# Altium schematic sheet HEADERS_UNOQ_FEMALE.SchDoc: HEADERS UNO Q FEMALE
size A3; Author: Silvio Navaretti; CompanyName: Arduino SRL; DrawnBy: Silvio Navaretti; Engineer: Silvio Navaretti; Organization: Arduino SRL; DocumentNumber: ASX00083; SheetNumber: 3; SheetTotal: 11; RevAuthor: Silvio Navaretti
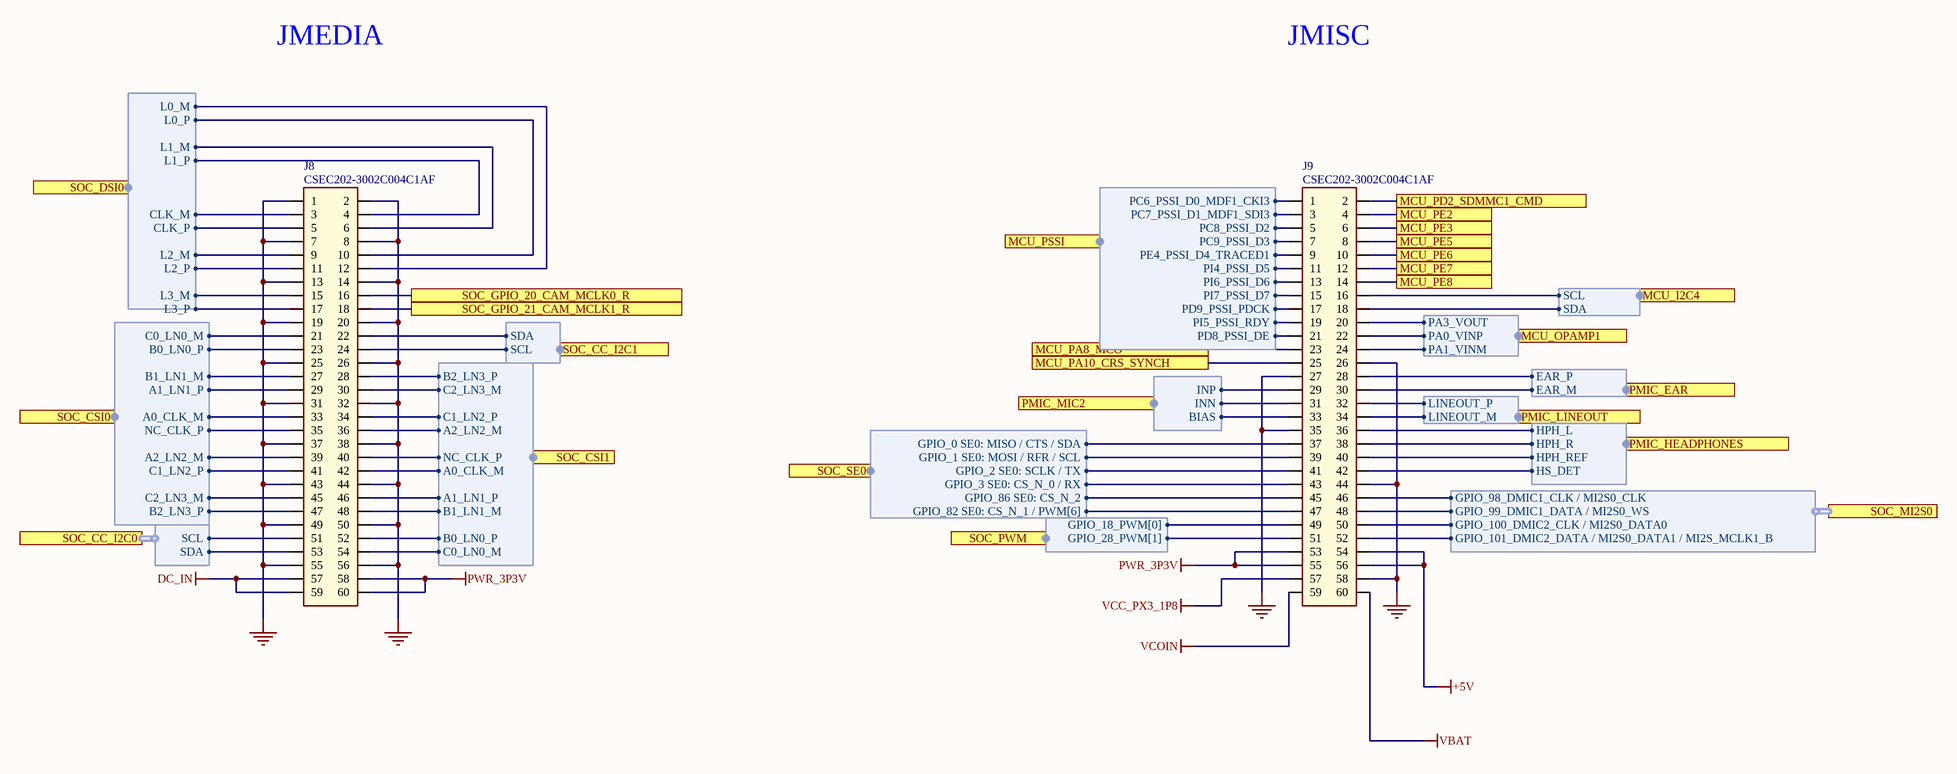
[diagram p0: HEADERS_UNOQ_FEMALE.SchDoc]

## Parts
J8  CSEC202-3002C004C1AF  [CSEC202-3002C004C1AF]
J9  CSEC202-3002C004C1AF  [CSEC202-3002C004C1AF]

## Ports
MCU_I2C4 (harness I2C), MCU_OPAMP1 (harness MCU_OPAMP), MCU_PA8_MCO, MCU_PA10_CRS_SYNCH, MCU_PD2_SDMMC1_CMD, MCU_PE2, MCU_PE3, MCU_PE5, MCU_PE6, MCU_PE7, MCU_PE8, MCU_PSSI (harness PSSI_MCU), PMIC_EAR (harness EAT), PMIC_HEADPHONES (harness HEADPHONES), PMIC_LINEOUT (harness LINEOUT), PMIC_MIC2 (harness MIC), SOC_CC_I2C0 (harness I2C), SOC_CC_I2C1 (harness I2C), SOC_CSI0 (harness IMOLA_CSI), SOC_CSI1 (harness IMOLA_CSI), SOC_DSI0 (harness IMOLA_DSI), SOC_GPIO_20_CAM_MCLK0_R, SOC_GPIO_21_CAM_MCLK1_R, SOC_MI2S0 (harness SOC_I2S), SOC_PWM (harness SOC_PWM), SOC_SE0 (harness SOC_GPIO)

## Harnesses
IMOLA_DSI: L1_P, L1_M, L3_P, L3_M, CLK_P, CLK_M, L0_P, L0_M, L2_P, L2_M
I2C: SDA, SCL
IMOLA_CSI: C2_LN3_M, A2_LN2_M, C1_LN2_P, C0_LN0_M, B0_LN0_P, A0_CLK_M, NC_CLK_P, B1_LN1_M, A1_LN1_P, B2_LN3_P
PSSI_MCU: PC6_PSSI_D0_MDF1_CKI3, PC7_PSSI_D1_MDF1_SDI3, PC8_PSSI_D2, PC9_PSSI_D3, PE4_PSSI_D4_TRACED1, PI4_PSSI_D5, PI6_PSSI_D6, PI7_PSSI_D7, PD9_PSSI_PDCK, PI5_PSSI_RDY, PD8_PSSI_DE
MCU_OPAMP: PA3_VOUT, PA0_VINP, PA1_VINM
EAT: EAR_P, EAR_M
MIC: INP, INN, BIAS
LINEOUT: LINEOUT_P, LINEOUT_M
HEADPHONES: HPH_L, HPH_R, HPH_REF, HS_DET
SOC_GPIO: GPIO_0 SE0: MISO / CTS / SDA, GPIO_1 SE0: MOSI / RFR / SCL, GPIO_2 SE0: SCLK / TX, GPIO_3 SE0: CS_N_0 / RX, GPIO_86 SE0: CS_N_2, GPIO_82 SE0: CS_N_1 / PWM[6]
SOC_PWM: GPIO_18_PWM[0], GPIO_28_PWM[1]
SOC_I2S: GPIO_98_DMIC1_CLK / MI2S0_CLK, GPIO_99_DMIC1_DATA / MI2S0_WS, GPIO_100_DMIC2_CLK / MI2S0_DATA0, GPIO_101_DMIC2_DATA / MI2S0_DATA1 / MI2S_MCLK1_B

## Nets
+5V: J9.54 J9.56
DC_IN: J8.57 J8.59
GND: J8.1 J8.2 J8.7 J8.8 J8.13 J8.14 J8.19 J8.20 J8.25 J8.26 J8.31 J8.32 J8.37 J8.38 J8.43 J8.44 J8.49 J8.50 J8.55 J8.56 J9.26 J9.27 J9.35 J9.44 J9.58
PWR_3P3V: J8.58 J8.60 J9.53 J9.55
VBAT: J9.60
VCC_PX3_1P8: J9.57
VCOIN: J9.59
MCU_PA8_MCO: J9.23 ; port MCU_PA8_MCO
MCU_PA10_CRS_SYNCH: J9.25 ; port MCU_PA10_CRS_SYNCH
MCU_PD2_SDMMC1_CMD: J9.2 ; port MCU_PD2_SDMMC1_CMD
MCU_PE2: J9.4 ; port MCU_PE2
MCU_PE3: J9.6 ; port MCU_PE3
MCU_PE5: J9.8 ; port MCU_PE5
MCU_PE6: J9.10 ; port MCU_PE6
MCU_PE7: J9.12 ; port MCU_PE7
MCU_PE8: J9.14 ; port MCU_PE8
SOC_GPIO_20_CAM_MCLK0_R: J8.16 ; port SOC_GPIO_20_CAM_MCLK0_R
SOC_GPIO_21_CAM_MCLK1_R: J8.18 ; port SOC_GPIO_21_CAM_MCLK1_R
NetJ8_3: J8.3 ; port SOC_DSI0.CLK_M
NetJ8_4: J8.4 ; port SOC_DSI0.L1_P
NetJ8_5: J8.5 ; port SOC_DSI0.CLK_P
NetJ8_6: J8.6 ; port SOC_DSI0.L1_M
NetJ8_9: J8.9 ; port SOC_DSI0.L2_M
NetJ8_10: J8.10 ; port SOC_DSI0.L0_P
NetJ8_11: J8.11 ; port SOC_DSI0.L2_P
NetJ8_12: J8.12 ; port SOC_DSI0.L0_M
NetJ8_15: J8.15 ; port SOC_DSI0.L3_M
NetJ8_17: J8.17 ; port SOC_DSI0.L3_P
NetJ8_21: J8.21 ; port SOC_CSI0.C0_LN0_M
NetJ8_22: J8.22 ; port SOC_CC_I2C1.SDA
NetJ8_23: J8.23 ; port SOC_CSI0.B0_LN0_P
NetJ8_24: J8.24 ; port SOC_CC_I2C1.SCL
NetJ8_27: J8.27 ; port SOC_CSI0.B1_LN1_M
NetJ8_28: J8.28 ; port SOC_CSI1.B2_LN3_P
NetJ8_29: J8.29 ; port SOC_CSI0.A1_LN1_P
NetJ8_30: J8.30 ; port SOC_CSI1.C2_LN3_M
NetJ8_33: J8.33 ; port SOC_CSI0.A0_CLK_M
NetJ8_34: J8.34 ; port SOC_CSI1.C1_LN2_P
NetJ8_35: J8.35 ; port SOC_CSI0.NC_CLK_P
NetJ8_36: J8.36 ; port SOC_CSI1.A2_LN2_M
NetJ8_39: J8.39 ; port SOC_CSI0.A2_LN2_M
NetJ8_40: J8.40 ; port SOC_CSI1.NC_CLK_P
NetJ8_41: J8.41 ; port SOC_CSI0.C1_LN2_P
NetJ8_42: J8.42 ; port SOC_CSI1.A0_CLK_M
NetJ8_45: J8.45 ; port SOC_CSI0.C2_LN3_M
NetJ8_46: J8.46 ; port SOC_CSI1.A1_LN1_P
NetJ8_47: J8.47 ; port SOC_CSI0.B2_LN3_P
NetJ8_48: J8.48 ; port SOC_CSI1.B1_LN1_M
NetJ8_51: J8.51 ; port SOC_CC_I2C0.SCL
NetJ8_52: J8.52 ; port SOC_CSI1.B0_LN0_P
NetJ8_53: J8.53 ; port SOC_CC_I2C0.SDA
NetJ8_54: J8.54 ; port SOC_CSI1.C0_LN0_M
NetJ9_1: J9.1 ; port MCU_PSSI.PC6_PSSI_D0_MDF1_CKI3
NetJ9_3: J9.3 ; port MCU_PSSI.PC7_PSSI_D1_MDF1_SDI3
NetJ9_5: J9.5 ; port MCU_PSSI.PC8_PSSI_D2
NetJ9_7: J9.7 ; port MCU_PSSI.PC9_PSSI_D3
NetJ9_9: J9.9 ; port MCU_PSSI.PE4_PSSI_D4_TRACED1
NetJ9_11: J9.11 ; port MCU_PSSI.PI4_PSSI_D5
NetJ9_13: J9.13 ; port MCU_PSSI.PI6_PSSI_D6
NetJ9_15: J9.15 ; port MCU_PSSI.PI7_PSSI_D7
NetJ9_16: J9.16 ; port MCU_I2C4.SCL
NetJ9_17: J9.17 ; port MCU_PSSI.PD9_PSSI_PDCK
NetJ9_18: J9.18 ; port MCU_I2C4.SDA
NetJ9_19: J9.19 ; port MCU_PSSI.PI5_PSSI_RDY
NetJ9_20: J9.20 ; port MCU_OPAMP1.PA3_VOUT
NetJ9_21: J9.21 ; port MCU_PSSI.PD8_PSSI_DE
NetJ9_22: J9.22 ; port MCU_OPAMP1.PA0_VINP
NetJ9_24: J9.24 ; port MCU_OPAMP1.PA1_VINM
NetJ9_28: J9.28 ; port PMIC_EAR.EAR_P
NetJ9_29: J9.29 ; port PMIC_MIC2.INP
NetJ9_30: J9.30 ; port PMIC_EAR.EAR_M
NetJ9_31: J9.31 ; port PMIC_MIC2.INN
NetJ9_32: J9.32 ; port PMIC_LINEOUT.LINEOUT_P
NetJ9_33: J9.33 ; port PMIC_MIC2.BIAS
NetJ9_34: J9.34 ; port PMIC_LINEOUT.LINEOUT_M
NetJ9_36: J9.36 ; port PMIC_HEADPHONES.HPH_L
NetJ9_37: J9.37 ; port SOC_SE0.GPIO_0 SE0: MISO / CTS / SDA
NetJ9_38: J9.38 ; port PMIC_HEADPHONES.HPH_R
NetJ9_39: J9.39 ; port SOC_SE0.GPIO_1 SE0: MOSI / RFR / SCL
NetJ9_40: J9.40 ; port PMIC_HEADPHONES.HPH_REF
NetJ9_41: J9.41 ; port SOC_SE0.GPIO_2 SE0: SCLK / TX
NetJ9_42: J9.42 ; port PMIC_HEADPHONES.HS_DET
NetJ9_43: J9.43 ; port SOC_SE0.GPIO_3 SE0: CS_N_0 / RX
NetJ9_45: J9.45 ; port SOC_SE0.GPIO_86 SE0: CS_N_2
NetJ9_46: J9.46 ; port SOC_MI2S0.GPIO_98_DMIC1_CLK / MI2S0_CLK
NetJ9_47: J9.47 ; port SOC_SE0.GPIO_82 SE0: CS_N_1 / PWM[6]
NetJ9_48: J9.48 ; port SOC_MI2S0.GPIO_99_DMIC1_DATA / MI2S0_WS
NetJ9_49: J9.49 ; port SOC_PWM.GPIO_18_PWM[0]
NetJ9_50: J9.50 ; port SOC_MI2S0.GPIO_100_DMIC2_CLK / MI2S0_DATA0
NetJ9_51: J9.51 ; port SOC_PWM.GPIO_28_PWM[1]
NetJ9_52: J9.52 ; port SOC_MI2S0.GPIO_101_DMIC2_DATA / MI2S0_DATA1 / MI2S_MCLK1_B

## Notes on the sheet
- JMEDIA
- JMISC

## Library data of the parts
J8 J9 = J0575-A.2: CONN HEADER FEMALE VERTICAL SMD 1.27mm 2x30 POS heigth 4.6mm FIXING PINS; Manufacturer: Greenconn; Code Arduino: J0575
